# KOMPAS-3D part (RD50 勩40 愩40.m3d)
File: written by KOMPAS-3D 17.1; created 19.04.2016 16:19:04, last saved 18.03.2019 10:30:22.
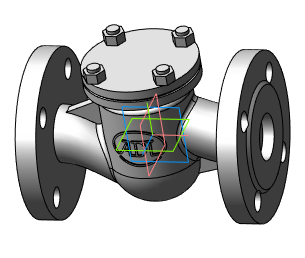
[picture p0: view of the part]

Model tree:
1. Операция без истории:3  (labels: Сталь 20  ГОСТ 1050-88)

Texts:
  RD50 Ду15 Ру40
  RD50 Ду20 Ру40
  RD50 Ду25 Ру40
  RD50 Ду32 Ру40
  RD50 Ду40 Ру40
  RD50 Ду50 Ру40
  RD50 Ду65 Ру40
  RD50 Ду80 Ру40
  RD50 Ду100 Ру40
  RD50 Ду125 Ру40
  RD50 Ду150 Ру40
  RD50 Ду200 Ру40
  RD50 Ду250 Ру40
  RD50 Ду300 Ру40
  RD50 Ду350 Ру40
  RD50 Ду400 Ру40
